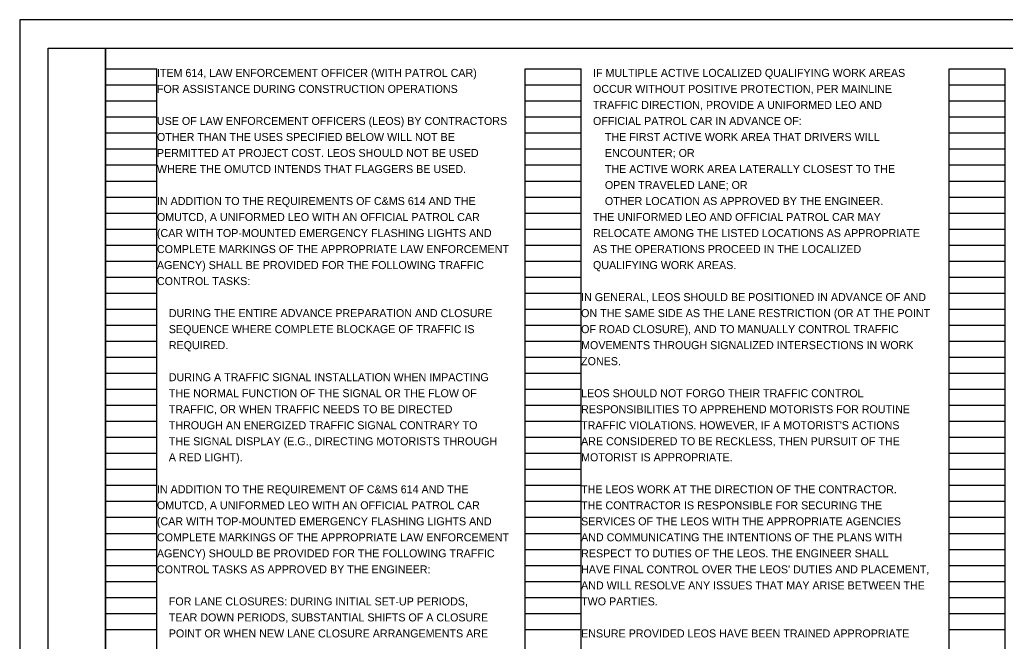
# Model space of a CAD drawing. Extents: x -33.9 to 34, y -0.4 to 22.
# Drawn here: x 0 to 17.24, y 11.13 to 22 of the extents above; entities that cross this region are included whole.
import ezdxf

# ---------------------------------------------------------------- set-up
doc = ezdxf.new("R2010")
doc.units = 0
for name, color, linetype in [('SH_Border', 7, 'Continuous'), ('SH_Cut_Line', 7, 'Continuous'), ('SH_Data', 7, 'Continuous'), ('SH_Text', 7, 'Continuous')]:
    doc.layers.add(name, color=color, linetype=linetype)

msp = doc.modelspace()

# ---------------------------------------------------------------- linework, layer by layer
at = {"layer": 'SH_Border'}
for points in [[(0.5, 21.5), (1.5, 21.5), (1.5, 0.5), (0.5, 0.5)], [(1.5, 21.5), (33.5, 21.5), (33.5, 0.5), (1.5, 0.5)]]:
    msp.add_lwpolyline(points, close=True, dxfattribs=at)
at = {"layer": 'SH_Cut_Line'}
msp.add_lwpolyline([(0, 0), (34, 0), (34, 22), (0, 22)], close=True, dxfattribs=at)
at = {"layer": 'SH_Data'}
for p, q in [((1.5, 0.98), (1.5, 21.14)), ((1.5, 21.14), (2.4, 21.14)), ((2.4, 0.98), (2.4, 21.14)), ((8.84, 0.98), (8.84, 21.14)), ((8.84, 21.14), (9.82, 21.14)), ((9.82, 0.98), (9.82, 21.14)), ((16.26, 0.98), (16.26, 21.14)), ((16.26, 21.14), (17.24, 21.14)), ((17.24, 0.98), (17.24, 21.14)), ((1.5, 20.86), (2.4, 20.86)), ((8.84, 20.86), (9.82, 20.86)), ((16.26, 20.86), (17.24, 20.86)), ((1.5, 20.58), (2.4, 20.58)), ((8.84, 20.58), (9.82, 20.58)), ((16.26, 20.58), (17.24, 20.58)), ((1.5, 20.3), (2.4, 20.3)), ((8.84, 20.3), (9.82, 20.3)), ((16.26, 20.3), (17.24, 20.3)), ((1.5, 20.02), (2.4, 20.02)), ((8.84, 20.02), (9.82, 20.02)), ((16.26, 20.02), (17.24, 20.02)), ((1.5, 19.74), (2.4, 19.74)), ((8.84, 19.74), (9.82, 19.74)), ((16.26, 19.74), (17.24, 19.74)), ((1.5, 19.46), (2.4, 19.46)), ((8.84, 19.46), (9.82, 19.46)), ((16.26, 19.46), (17.24, 19.46)), ((1.5, 19.18), (2.4, 19.18)), ((8.84, 19.18), (9.82, 19.18)), ((16.26, 19.18), (17.24, 19.18)), ((1.5, 18.9), (2.4, 18.9)), ((8.84, 18.9), (9.82, 18.9)), ((16.26, 18.9), (17.24, 18.9)), ((1.5, 18.62), (2.4, 18.62)), ((8.84, 18.62), (9.82, 18.62)), ((16.26, 18.62), (17.24, 18.62)), ((1.5, 18.34), (2.4, 18.34)), ((8.84, 18.34), (9.82, 18.34)), ((16.26, 18.34), (17.24, 18.34)), ((1.5, 18.06), (2.4, 18.06)), ((8.84, 18.06), (9.82, 18.06)), ((16.26, 18.06), (17.24, 18.06)), ((1.5, 17.78), (2.4, 17.78)), ((8.84, 17.78), (9.82, 17.78)), ((16.26, 17.78), (17.24, 17.78)), ((1.5, 17.5), (2.4, 17.5)), ((8.84, 17.5), (9.82, 17.5)), ((16.26, 17.5), (17.24, 17.5)), ((1.5, 17.22), (2.4, 17.22)), ((8.84, 17.22), (9.82, 17.22)), ((16.26, 17.22), (17.24, 17.22)), ((1.5, 16.94), (2.4, 16.94)), ((8.84, 16.94), (9.82, 16.94)), ((16.26, 16.94), (17.24, 16.94)), ((1.5, 16.66), (2.4, 16.66)), ((8.84, 16.66), (9.82, 16.66)), ((16.26, 16.66), (17.24, 16.66)), ((1.5, 16.38), (2.4, 16.38)), ((8.84, 16.38), (9.82, 16.38)), ((16.26, 16.38), (17.24, 16.38)), ((1.5, 16.1), (2.4, 16.1)), ((8.84, 16.1), (9.82, 16.1)), ((16.26, 16.1), (17.24, 16.1)), ((1.5, 15.82), (2.4, 15.82)), ((8.84, 15.82), (9.82, 15.82)), ((16.26, 15.82), (17.24, 15.82)), ((1.5, 15.54), (2.4, 15.54)), ((8.84, 15.54), (9.82, 15.54)), ((16.26, 15.54), (17.24, 15.54)), ((1.5, 15.26), (2.4, 15.26)), ((8.84, 15.26), (9.82, 15.26)), ((16.26, 15.26), (17.24, 15.26)), ((1.5, 14.98), (2.4, 14.98)), ((8.84, 14.98), (9.82, 14.98)), ((16.26, 14.98), (17.24, 14.98)), ((1.5, 14.7), (2.4, 14.7)), ((8.84, 14.7), (9.82, 14.7)), ((16.26, 14.7), (17.24, 14.7)), ((1.5, 14.42), (2.4, 14.42)), ((8.84, 14.42), (9.82, 14.42)), ((16.26, 14.42), (17.24, 14.42)), ((1.5, 14.14), (2.4, 14.14)), ((8.84, 14.14), (9.82, 14.14)), ((16.26, 14.14), (17.24, 14.14)), ((1.5, 13.86), (2.4, 13.86)), ((8.84, 13.86), (9.82, 13.86)), ((16.26, 13.86), (17.24, 13.86)), ((1.5, 13.58), (2.4, 13.58)), ((8.84, 13.58), (9.82, 13.58)), ((16.26, 13.58), (17.24, 13.58)), ((1.5, 13.3), (2.4, 13.3)), ((8.84, 13.3), (9.82, 13.3)), ((16.26, 13.3), (17.24, 13.3)), ((1.5, 13.02), (2.4, 13.02)), ((8.84, 13.02), (9.82, 13.02)), ((16.26, 13.02), (17.24, 13.02)), ((1.5, 12.74), (2.4, 12.74)), ((8.84, 12.74), (9.82, 12.74)), ((16.26, 12.74), (17.24, 12.74)), ((1.5, 12.46), (2.4, 12.46)), ((8.84, 12.46), (9.82, 12.46)), ((16.26, 12.46), (17.24, 12.46)), ((1.5, 12.18), (2.4, 12.18)), ((8.84, 12.18), (9.82, 12.18)), ((16.26, 12.18), (17.24, 12.18)), ((1.5, 11.9), (2.4, 11.9)), ((8.84, 11.9), (9.82, 11.9)), ((16.26, 11.9), (17.24, 11.9)), ((1.5, 11.62), (2.4, 11.62)), ((8.84, 11.62), (9.82, 11.62)), ((16.26, 11.62), (17.24, 11.62)), ((1.5, 11.34), (2.4, 11.34)), ((8.84, 11.34), (9.82, 11.34)), ((16.26, 11.34), (17.24, 11.34))]:
    msp.add_line(p, q, dxfattribs=at)

# ---------------------------------------------------------------- texts
at = {"layer": 'SH_Text'}
for s, p in [('ITEM 614, LAW ENFORCEMENT OFFICER (WITH PATROL CAR)', (2.4, 21)), ('    IF MULTIPLE ACTIVE LOCALIZED QUALIFYING WORK AREAS', (9.82, 21)), ('FOR ASSISTANCE DURING CONSTRUCTION OPERATIONS', (2.4, 20.72)), ('    OCCUR WITHOUT POSITIVE PROTECTION, PER MAINLINE', (9.82, 20.72)), ('    TRAFFIC DIRECTION, PROVIDE A UNIFORMED LEO AND', (9.82, 20.44)), ('USE OF LAW ENFORCEMENT OFFICERS (LEOS) BY CONTRACTORS', (2.4, 20.16)), ('    OFFICIAL PATROL CAR IN ADVANCE OF:', (9.82, 20.16)), ('OTHER THAN THE USES SPECIFIED BELOW WILL NOT BE', (2.4, 19.88)), ('        THE FIRST ACTIVE WORK AREA THAT DRIVERS WILL', (9.82, 19.88)), ('PERMITTED AT PROJECT COST. LEOS SHOULD NOT BE USED', (2.4, 19.6)), ('        ENCOUNTER; OR', (9.82, 19.6)), ('WHERE THE OMUTCD INTENDS THAT FLAGGERS BE USED.', (2.4, 19.32)), ('        THE ACTIVE WORK AREA LATERALLY CLOSEST TO THE', (9.82, 19.32)), ('        OPEN TRAVELED LANE; OR', (9.82, 19.04)), ('IN ADDITION TO THE REQUIREMENTS OF C&MS 614 AND THE', (2.4, 18.76)), ('        OTHER LOCATION AS APPROVED BY THE ENGINEER.', (9.82, 18.76)), ('OMUTCD, A UNIFORMED LEO WITH AN OFFICIAL PATROL CAR', (2.4, 18.48)), ('    THE UNIFORMED LEO AND OFFICIAL PATROL CAR MAY', (9.82, 18.48)), ('(CAR WITH TOP-MOUNTED EMERGENCY FLASHING LIGHTS AND', (2.4, 18.2)), ('    RELOCATE AMONG THE LISTED LOCATIONS AS APPROPRIATE', (9.82, 18.2)), ('COMPLETE MARKINGS OF THE APPROPRIATE LAW ENFORCEMENT', (2.4, 17.92)), ('    AS THE OPERATIONS PROCEED IN THE LOCALIZED', (9.82, 17.92)), ('AGENCY) SHALL BE PROVIDED FOR THE FOLLOWING TRAFFIC', (2.4, 17.64)), ('    QUALIFYING WORK AREAS.', (9.82, 17.64)), ('CONTROL TASKS:', (2.4, 17.36)), ('IN GENERAL, LEOS SHOULD BE POSITIONED IN ADVANCE OF AND', (9.82, 17.08)), ('    DURING THE ENTIRE ADVANCE PREPARATION AND CLOSURE', (2.4, 16.8)), ('ON THE SAME SIDE AS THE LANE RESTRICTION (OR AT THE POINT', (9.82, 16.8)), ('    SEQUENCE WHERE COMPLETE BLOCKAGE OF TRAFFIC IS', (2.4, 16.52)), ('OF ROAD CLOSURE), AND TO MANUALLY CONTROL TRAFFIC', (9.82, 16.52)), ('    REQUIRED.', (2.4, 16.24)), ('MOVEMENTS THROUGH SIGNALIZED INTERSECTIONS IN WORK', (9.82, 16.24)), ('ZONES.', (9.82, 15.96)), ('    DURING A TRAFFIC SIGNAL INSTALLATION WHEN IMPACTING', (2.4, 15.68)), ('    THE NORMAL FUNCTION OF THE SIGNAL OR THE FLOW OF', (2.4, 15.4)), ('LEOS SHOULD NOT FORGO THEIR TRAFFIC CONTROL', (9.82, 15.4)), ('    TRAFFIC, OR WHEN TRAFFIC NEEDS TO BE DIRECTED', (2.4, 15.12)), ('RESPONSIBILITIES TO APPREHEND MOTORISTS FOR ROUTINE', (9.82, 15.12)), ('    THROUGH AN ENERGIZED TRAFFIC SIGNAL CONTRARY TO', (2.4, 14.84)), ("TRAFFIC VIOLATIONS. HOWEVER, IF A MOTORIST'S ACTIONS", (9.82, 14.84)), ('    THE SIGNAL DISPLAY (E.G., DIRECTING MOTORISTS THROUGH', (2.4, 14.56)), ('ARE CONSIDERED TO BE RECKLESS, THEN PURSUIT OF THE', (9.82, 14.56)), ('    A RED LIGHT).', (2.4, 14.28)), ('MOTORIST IS APPROPRIATE.', (9.82, 14.28)), ('IN ADDITION TO THE REQUIREMENT OF C&MS 614 AND THE', (2.4, 13.72)), ('THE LEOS WORK AT THE DIRECTION OF THE CONTRACTOR.', (9.82, 13.72)), ('OMUTCD, A UNIFORMED LEO WITH AN OFFICIAL PATROL CAR', (2.4, 13.44)), ('THE CONTRACTOR IS RESPONSIBLE FOR SECURING THE', (9.82, 13.44)), ('(CAR WITH TOP-MOUNTED EMERGENCY FLASHING LIGHTS AND', (2.4, 13.16)), ('SERVICES OF THE LEOS WITH THE APPROPRIATE AGENCIES', (9.82, 13.16)), ('COMPLETE MARKINGS OF THE APPROPRIATE LAW ENFORCEMENT', (2.4, 12.88)), ('AND COMMUNICATING THE INTENTIONS OF THE PLANS WITH', (9.82, 12.88)), ('AGENCY) SHOULD BE PROVIDED FOR THE FOLLOWING TRAFFIC', (2.4, 12.6)), ('RESPECT TO DUTIES OF THE LEOS. THE ENGINEER SHALL', (9.82, 12.6)), ('CONTROL TASKS AS APPROVED BY THE ENGINEER:', (2.4, 12.32)), ("HAVE FINAL CONTROL OVER THE LEOS' DUTIES AND PLACEMENT,", (9.82, 12.32)), ('AND WILL RESOLVE ANY ISSUES THAT MAY ARISE BETWEEN THE', (9.82, 12.04)), ('    FOR LANE CLOSURES: DURING INITIAL SET-UP PERIODS,', (2.4, 11.76)), ('TWO PARTIES.', (9.82, 11.76)), ('    TEAR DOWN PERIODS, SUBSTANTIAL SHIFTS OF A CLOSURE', (2.4, 11.48)), ('    POINT OR WHEN NEW LANE CLOSURE ARRANGEMENTS ARE', (2.4, 11.2)), ('ENSURE PROVIDED LEOS HAVE BEEN TRAINED APPROPRIATE', (9.82, 11.2))]:
    msp.add_text(s, height=0.14, dxfattribs=at).set_placement(p)

doc.saveas('drawing.dxf')
